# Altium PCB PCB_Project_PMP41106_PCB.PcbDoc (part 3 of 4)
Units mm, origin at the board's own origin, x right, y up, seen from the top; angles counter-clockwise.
Board outline 190 x 100 mm, 2 copper layers (Top Layer, Bottom Layer), stack 1.646 mm thick; 219 components, 122 nets, 541 pads, 61 vias.
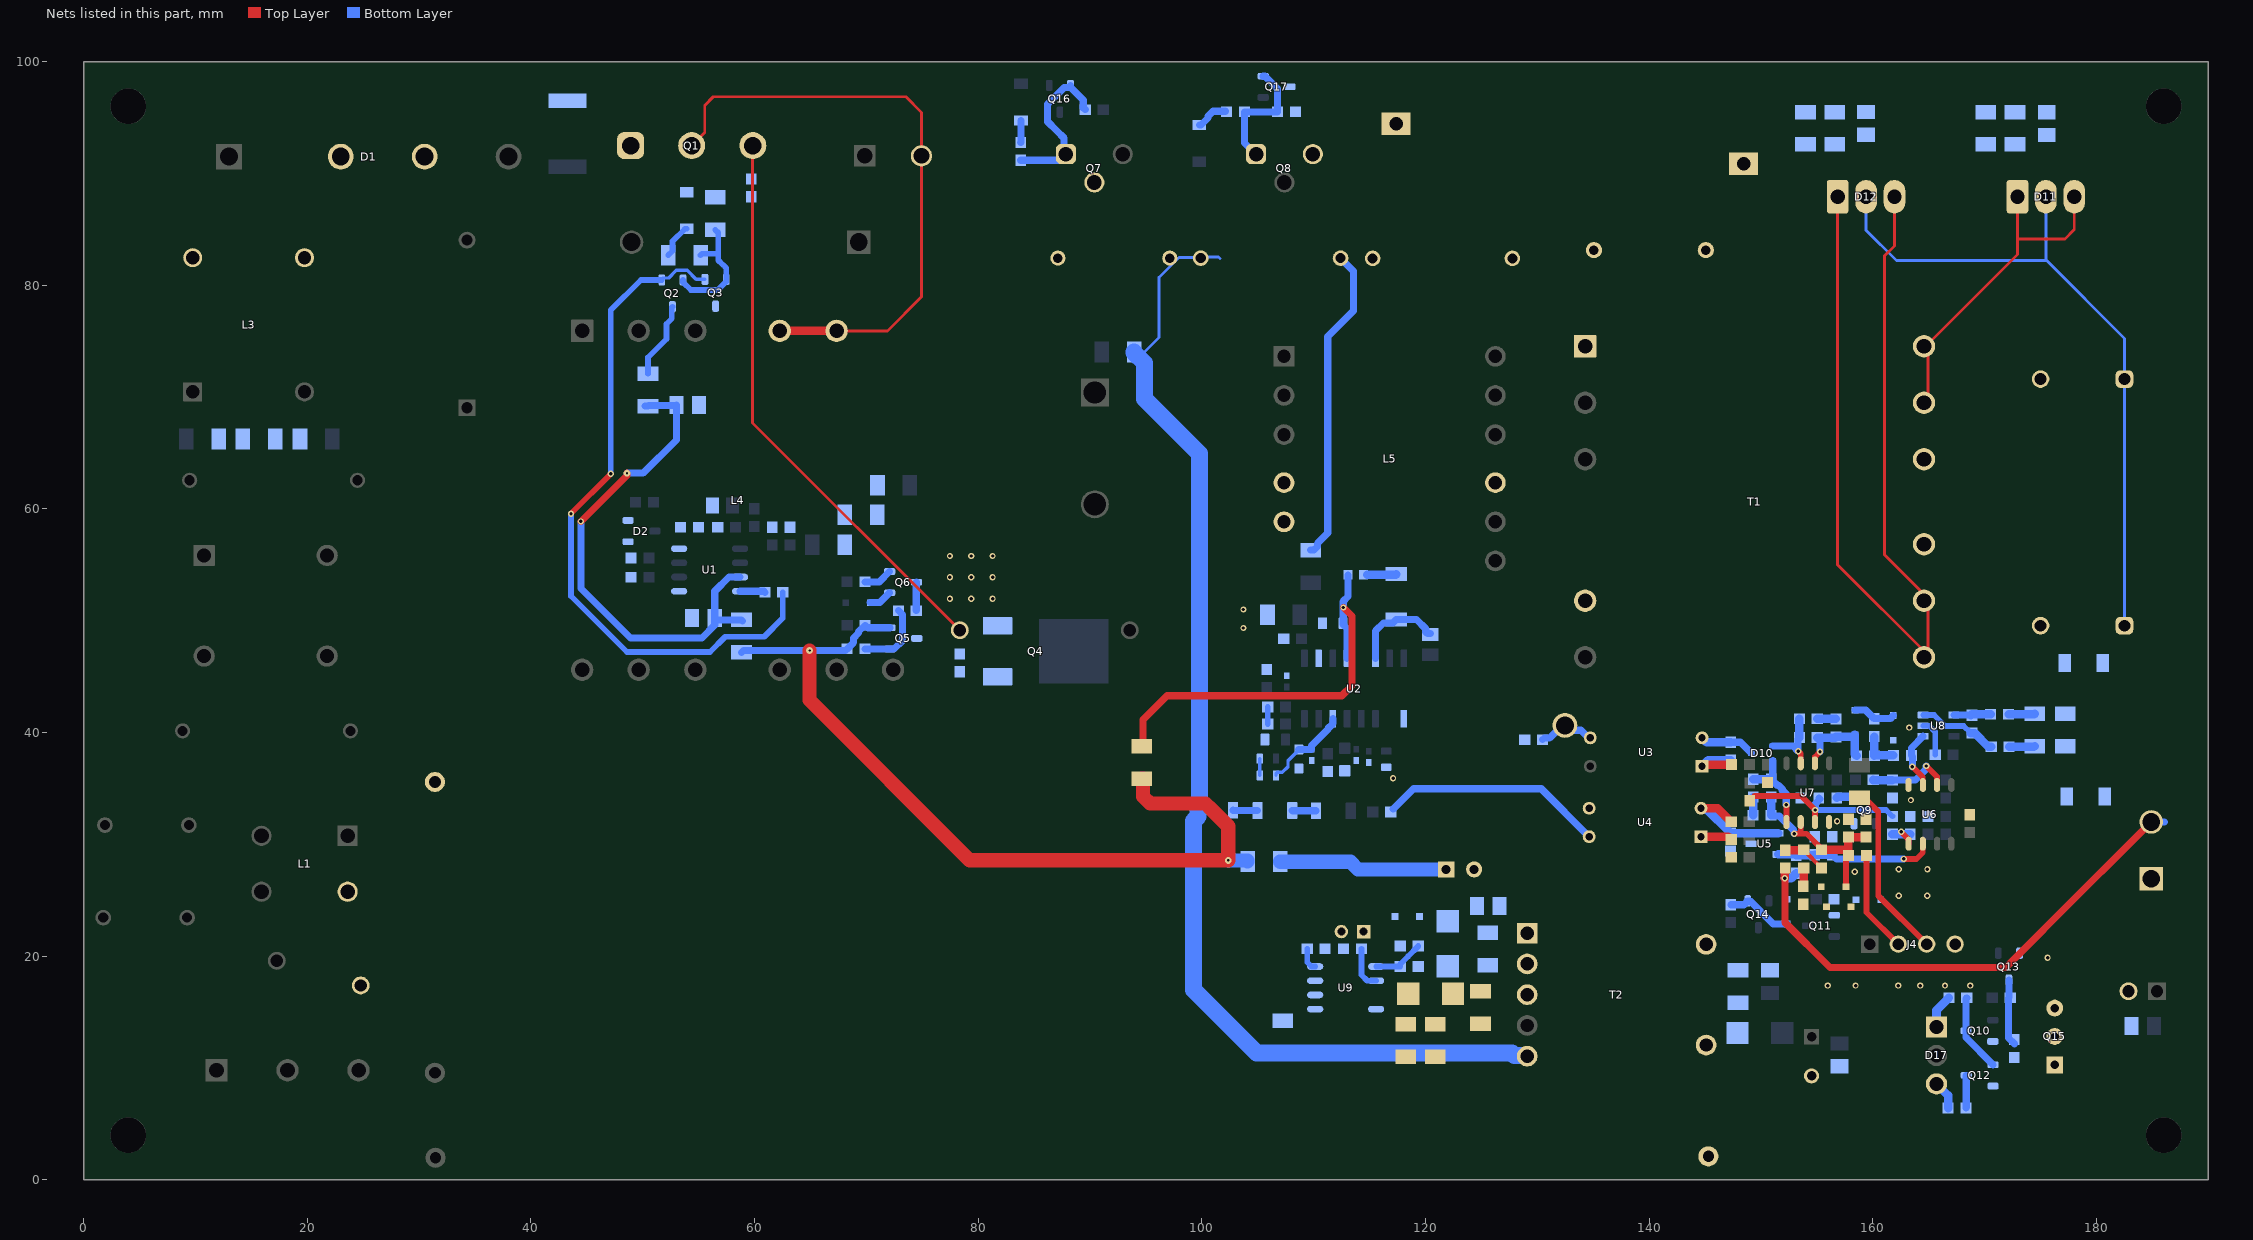
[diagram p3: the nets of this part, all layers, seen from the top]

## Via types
v1: diameter 0.559, hole 0.305, Top Layer to Bottom Layer, tented both sides, 50 vias
v2: diameter 0.61, hole 0.203, Top Layer to Bottom Layer, tented both sides, 9 vias
v3: diameter 0.559, hole 0.305, Top Layer to Bottom Layer, 2 vias

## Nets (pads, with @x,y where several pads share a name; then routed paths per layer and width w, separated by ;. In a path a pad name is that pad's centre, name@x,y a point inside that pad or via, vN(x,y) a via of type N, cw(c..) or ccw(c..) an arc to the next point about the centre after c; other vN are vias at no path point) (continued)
NetC17_2: C17.2 R27.1 R28.1 U2.12 | length 37.4
  Top Layer w0.635: R28.1@94.615,38.788 94.742,38.915 94.742,41.148 96.884,43.29 112.505,43.29 113.411,44.196 113.411,50.419 v3(112.649,51.181)
  Top Layer w1.27: R28.1@94.488,38.803 94.503,38.788 R28.1@94.615,38.788
  Bottom Layer w0.635: C17.2@112.634,49.659 112.979,49.314 U2.12@112.979,46.636 ; C17.2@112.634,49.784 112.634,51.736 113.067,52.168 R27.1@113.067,54.102
NetC18_2: C18.2 D9.1 U2.14 | length 8.4
  Bottom Layer w0.635: U2.14@115.519,46.636 115.519,49.098 116.225,49.804 117.071,49.804 D9.1@117.373,50.106 119.185,50.106 120.014,49.277 120.014,49.011 120.155,48.87 C18.2@120.421,48.87
NetC19_1: C19.1 R35.1 R37.2 U2.6 | length 8.1
  Bottom Layer w0.305: R35.1@106.626,36.165 106.626,36.34 106.748,36.462 107.201,36.462 107.696,36.957 107.696,37.478 108.661,38.443 R37.2@108.661,38.493
  Bottom Layer w0.635: R37.2@108.661,38.493 108.667,38.498 C19.1@109.804,38.498 109.804,38.824 111.257,40.277 111.257,40.344 111.709,40.796 U2.6@111.709,41.236
NetC22_2: C22.2 C23.1 C24.1 T1.5 | length 28.2
  Bottom Layer w0.635: C24.1@109.728,56.314 110.003,56.314 110.335,56.647 110.335,56.921 111.252,57.838 111.252,75.422 113.538,77.708 113.538,81.282 C22.2@112.447,82.372
NetC27_1: C27.1 R42.1 U4.2 U5.1 | length 11
  Top Layer w0.762: U4.2@144.624,33.23 146.114,33.23 R42.1@147.333,32.011
  Bottom Layer w0.762: U4.2@144.624,33.23 145.047,33.23 C27.1@147.269,31.007 147.272,31.005 U5.1@151.517,31.005
NetC29_1: C29.1 R43.1 R44.2 U5.2 U6.6 | length 14.2
  Top Layer w0.508: v1(162.763,28.702) 163.881,28.702 164.465,29.286 U6.6@164.465,30.065
  Bottom Layer w0.635: C29.1@156.362,29.077 156.737,28.702 v1(162.763,28.702)
  Bottom Layer w0.762: U5.2@151.517,29.105 153.058,29.105 R43.1@153.137,29.026 154.737,29.026 R44.2@154.788,29.077 C29.1@156.362,29.077
NetC31_1: C31.1 C34.2 D10.2 U7.1 | length 7.8
  Top Layer w0.508: v1(152.248,33.535) 152.248,33.382 152.273,33.357 U7.1@152.273,32.002
  Bottom Layer w0.635: D10.2@151.039,37.507 151.039,35.894 150.939,35.795 151.484,35.251 151.591,35.251 151.894,34.948 151.894,34.841 152.248,34.487 v1(152.248,33.535)
  Bottom Layer w0.762: C31.1@149.301,35.833 C34.2@150.901,35.833 C34.2@150.939,35.795
NetC31_2: C31.2 R53.2 | length 1.6
  Bottom Layer w0.762: R53.2@149.289,32.62 149.301,32.633 C31.2@149.301,34.233
NetC32_1: C32.1 C33.2 D10.1 U7.7 | length 6.6
  Top Layer w0.508: v1(153.314,38.335) 153.543,38.107 U7.7@153.543,37.252
  Bottom Layer w0.635: D10.1@151.039,38.807 152.842,38.807 v1(153.314,38.335) 153.314,39.44 C33.2@153.429,39.554
  Bottom Layer w0.762: C33.2@153.429,39.554 C32.1@153.429,41.231
NetC32_2: C32.2 R54.1 | length 1.7
  Bottom Layer w0.762: C32.2@155.029,41.231 155.042,41.218 R54.1@156.693,41.218
NetC33_1: C33.1 D13.1 R54.2 R60.1 U7.6 | length 8
  Top Layer w0.508: U7.6@154.813,37.252 154.813,37.827 v1(155.27,38.284)
  Bottom Layer w0.635: C33.1@155.029,39.554 155.27,39.313 v1(155.27,38.284)
  Bottom Layer w0.762: C33.1@155.029,39.554 156.629,39.554 R54.2@156.693,39.618 158.212,39.618 D13.1@158.394,39.801 158.394,38.069 R60.1@158.534,37.929
NetC37_2: C37.2 R48.2 R49.2
NetC38_2: C38.2 R50.2 R51.2
NetC40_1: C40.1 R60.2 R61.2 | length 3.4
  Bottom Layer w0.762: C40.1@160.122,39.643 160.134,39.631 R60.2@160.134,37.929 160.16,37.954 R61.2@161.836,37.954
NetC40_2: C40.2 D13.2 D15.1 | length 3.9
  Bottom Layer w0.635: D13.2@158.394,42.001 159.364,42.001 C40.2@160.122,41.243 161.549,41.243 D15.1@161.823,41.518
NetC42_1: C42.1 R87.1 | length 1.8
  Top Layer w0.762: C42.1@153.721,26.251 C42.1@153.81,26.34 ; C42.1@153.772,26.251 153.81,26.289 C42.1@153.81,26.34 ; R87.1@153.81,27.921 R87.1@153.81,27.889 C42.1@153.81,26.34
NetC42_2: C42.2 D14.1 D16.2
NetC45_1: C45.1 R67.1 U8.4 | length 3.3
  Bottom Layer w0.635: U8.4@167.237,41.571 168.735,41.571 C45.1@168.758,41.548
  Bottom Layer w0.762: C45.1@168.758,41.548 168.847,41.637 R67.1@170.523,41.637
NetC45_2: C45.2 R70.1 U8.3 | length 7.3
  Bottom Layer w0.508: U8.3@164.487,41.571 165.471,41.571 166.448,40.594 168.112,40.594 C45.2@168.758,39.948
  Bottom Layer w0.762: C45.2@168.758,39.948 169.1,39.948 170.332,38.716 R70.1@170.574,38.716
NetC46_2: C46.2 J2.1 R68.2 R69.2 R70.2 | length 2.3
  Bottom Layer w0.762: R70.2@172.174,38.716 174.399,38.716 R68.2@174.473,38.79
NetC48_1: C48.1 C50.1 D19.1 U9.6 | length 3.9
  Bottom Layer w0.508: C50.1@114.262,20.682 114.262,18.333 114.783,17.812 U9.6@115.577,17.812
NetC49_1: C49.1 C51.2 D19.2 D20.1 R74.2 | length 15.1
  Bottom Layer w1.27: R74.2@106.987,28.473 106.987,28.463 107.002,28.448 113.284,28.448 113.963,27.769 C49.1@121.838,27.769
NetC51_1: C51.1 R75.1
NetC52_2: C52.2 D21.1 R76.1
NetC53_2: C53.2 R81.2
NetC56_2: C56.2 J3.2 Q15.3
NetD1_2: D1.2 L3.4
NetD1_3: D1.3 L3.3
NetD4_1: D4.1 R12.2 | length 3.1
  Bottom Layer w0.508: R12.2@52.271,82.677 52.667,83.073 52.667,83.936 53.772,85.04 D4.1@53.924,85.04
NetD4_2: D4.2 Q1.1 R8.2 R9.2
NetD5_2: D5.2 L4.4 L4.5 Q1.2 | length 54.8
  Top Layer w0.254: Q1.2@54.356,92.488 55.539,93.671 55.539,96.081 56.308,96.85 73.533,96.85 74.93,95.453 74.93,91.421 74.93,78.969 71.88,75.918 L4.5@67.332,75.918
  Top Layer w0.762: L4.4@62.252,75.918 L4.5@67.332,75.918
NetD6_2: D6.2 Q6.1 | length 2.1
  Bottom Layer w0.635: D6.2@70.34,51.619 71.2,51.619 Q6.1@72.079,52.498
NetD7_1: D7.1 R29.1 | length 2
  Bottom Layer w0.635: R29.1@83.795,92.773 83.807,92.786 83.807,94.717 D7.1@83.82,94.73
NetD8_1: D8.1 R30.1 | length 2.9
  Bottom Layer w0.635: D8.1@99.771,94.322 99.924,94.322 100.555,94.953 100.555,95.106 101.004,95.555 R30.1@102.095,95.555
NetD9_2: D9.2 R27.2 | length 2.6
  Bottom Layer w0.762: R27.2@114.783,54.102 117.329,54.102 D9.2@117.373,54.146
NetD10_3: D10.3 R41.2 U3.2 | length 5
  Bottom Layer w0.635: R41.2@147.295,39.135 148.161,39.135 D10.3@149.139,38.157
  Bottom Layer w0.762: U3.2@144.725,39.529 145.119,39.135 R41.2@147.295,39.135
NetD11_1: D11.1 D11.3 R48.1 R49.1 T1.11 T1.12 | length 29.8
  Top Layer w0.254: T1.11@164.922,69.665 164.922,74.745 172.923,82.746 172.923,84.131 ; D11.1@172.923,87.865 172.923,84.131 ; D11.3@178.003,87.865 178.003,84.97 177.165,84.131 172.923,84.131
NetD12_1: D12.1 D12.3 R50.1 R51.1 T1.7 T1.8 | length 87.3
  Top Layer w0.254: D12.1@156.845,87.916 156.845,55.012 164.922,46.935 164.922,52.015 161.036,55.901 161.036,82.633 161.925,83.522 D12.3@161.925,87.916
NetD17_1: D17.1 R71.2 | length 3.1
  Bottom Layer w0.762: D17.1@165.684,13.665 165.684,15.176 R71.2@166.789,16.281
NetD17_3: D17.3 R72.2 | length 2.6
  Bottom Layer w0.762: D17.3@165.684,8.585 166.713,7.556 R72.2@166.713,6.426
NetD18_1: D18.1 Q11.1 R73.2
NetD20_2: D20.2 R75.2 R79.2 T2.2
NetD21_2: D21.2 R77.2
NetD22_2: D22.2 R81.1 T2.7
NetD23_1: D23.1 Q14.1 R82.2 | length 6.1
  Bottom Layer w0.635: R82.2@147.295,24.606 148.459,24.606 Q14.1@148.808,24.956 149.016,24.956 151.087,22.884 D23.1@152.349,22.884
NetF1_1: F1.1 L1.2 RV1.1 | length 0
  Top Layer w0.254: RV1.1@24.781,17.391 RV1.1@24.79,17.4
NetI_OPTO_1: I_OPTO.1 R38.2 U3.3 | length 5.1
  Bottom Layer w0.635: R38.2@130.467,39.37 130.624,39.528 131.095,39.528 132.08,40.513 132.588,40.513 132.889,40.212 133.903,40.212 134.586,39.529 U3.3@134.725,39.529
NetJ4_2: J4.2 R86.1 | length 9.1
  Top Layer w0.508: R86.1@159.423,29.007 159.423,23.925 J4.2@162.266,21.082
NetJ4_3: J4.3 R85.2 | length 15.8
  Top Layer w0.508: R85.2@158.801,34.174 159.222,34.174 160.477,32.918 160.477,25.411 J4.3@164.806,21.082
NetL5_9: L5.9 T1.1
NetQ2_1: Q2.1 Q3.1 R11.2 | length 61.8
  Top Layer w0.508: v1(43.586,59.57) 43.586,59.579 47.142,63.135 v1(47.142,63.144)
  Bottom Layer w0.305: Q2.1@51.704,80.473 51.704,80.497 51.852,80.645 52.324,80.645 53.005,81.326 53.962,81.326 54.764,80.524 Q3.1@55.565,80.524
  Bottom Layer w0.508: v1(43.586,59.57) 43.586,52.204 48.59,47.2 56.007,47.2 57.379,48.571 60.858,48.571 62.522,50.235 R11.2@62.522,52.534 ; v1(47.142,63.144) 47.142,77.775 49.841,80.473 Q2.1@51.704,80.473
NetQ2_2: Q2.2 Q3.2 R9.1 R12.1 | length 11.3
  Bottom Layer w0.508: Q2.2@53.604,80.473 53.604,80.273 54.307,79.57 56.711,79.57 57.465,80.324 Q3.2@57.465,80.524 57.465,81.544 57.167,81.841 57.142,81.841 56.746,82.237 56.746,82.804 ; R12.1@55.171,82.677 55.298,82.804 56.746,82.804 ; R9.1@56.49,84.949 56.746,84.692 56.746,82.804
NetQ2_3: Q2.3 R13.2 | length 6.9
  Bottom Layer w0.508: R13.2@50.47,72.087 50.47,73.546 52.121,75.197 52.121,76.538 52.608,77.025 52.608,78.027 Q2.3@52.654,78.073
NetQ4_1: Q4.1 Q5.3 R20.2
NetQ5_1: Q5.1 R21.1 R22.2 | length 6.5
  Bottom Layer w0.635: R21.1@69.863,47.479 72.094,47.479 Q5.1@72.104,47.469 72.481,47.469 73.228,48.216 73.228,50.54 R22.2@72.86,50.908
NetQ6_3: Q6.3 R22.1 | length 2.5
  Bottom Layer w0.635: R22.1@74.46,50.908 74.46,53.429 Q6.3@74.479,53.448
NetQ7_1: Q7.1 Q16.2 R29.2 R33.2 | length 14.9
  Bottom Layer w0.635: R29.2@83.795,91.173 87.26,91.173 87.812,91.726 87.884,91.726 87.684,91.926 87.684,93.139 86.995,93.828 86.208,94.615 86.208,96.206 87.692,97.69 88.232,97.69 Q16.2@88.25,97.707 ; Q16.2@88.25,97.872 Q16.2@88.25,97.707 ; R33.2@89.573,95.707 89.548,95.707 89.391,95.865 89.391,96.566 Q16.2@88.25,97.707
NetQ8_1: Q8.1 Q17.2 R30.2 R34.2 | length 10.9
  Bottom Layer w0.635: Q8.1@104.724,91.726 104.724,91.798 103.797,92.725 R30.2@103.797,95.504 R34.2@106.769,95.504 106.769,97.565 105.645,98.689 Q17.2@105.48,98.689
NetQ9_3: Q9.3 R55.1 | length 2.5
  Bottom Layer w0.762: R55.1@156.769,34.157 156.864,34.252 Q9.3@159.258,34.252
NetQ10_3: Q10.3 Q12.1 R71.1 | length 7
  Bottom Layer w0.635: R71.1@168.389,16.281 168.32,16.212 Q10.3@168.32,13.335 168.32,12.723 Q12.1@170.745,10.297
NetQ12_3: Q12.3 R72.1 | length 2.9
  Bottom Layer w0.635: R72.1@168.313,6.426 168.345,6.458 Q12.3@168.345,9.347
NetQ13_3: Q13.3 Q15.2 R83.1 R84.2 | length 5.9
  Bottom Layer w0.635: Q13.3@172.161,17.875 172.161,16.32 172.123,16.281 172.123,12.7 R84.2@172.644,12.179
NetR1_1: R1.1 R2.2
NetR2_1: R2.1 R3.2
NetR6_2: R6.2 U1.4
NetR11_1: R11.1 U1.8 | length 2.3
  Bottom Layer w0.635: U1.8@58.707,52.635 60.82,52.635 R11.1@60.922,52.534
NetR14_1: R14.1 R15.2
NetR15_1: R15.1 R16.2
NetR23_1: R23.1 R24.2 | length 1.5
  Bottom Layer w0.508: R23.1@105.88,40.767 R24.2@105.88,42.291
NetR32_1: R32.1 R35.2 | length 1.5
  Bottom Layer w0.305: R35.2@105.176,36.165 R32.1@105.176,37.663
NetR36_1: R36.1 U4.4 | length 20
  Bottom Layer w0.635: R36.1@117.108,33.161 118.923,34.976 130.338,34.976 U4.4@134.624,30.69
NetR39_1: R39.1 U4.1 | length 2.8
  Top Layer w0.762: U4.1@144.624,30.69 147.079,30.69 R39.1@147.333,30.436
NetR40_1: R40.1 R41.1 U3.1 | length 5.5
  Top Layer w0.762: U3.1@144.725,36.989 144.878,37.141 R40.1@147.358,37.141
  Bottom Layer w0.762: U3.1@144.725,36.989 145.272,37.535 R41.1@147.295,37.535
NetR45_1: R45.1 R46.2 U6.5 | length 2.9
  Top Layer w0.508: v1(162.535,31.122) 163.195,30.461 U6.5@163.195,30.065
  Bottom Layer w0.762: R45.1@161.747,30.906 R46.2@163.347,30.906
NetR58_1: R58.1 R59.2 U6.2 | length 7.5
  Top Layer w0.508: v1(164.77,37.014) 165.735,36.049 U6.2@165.735,35.315
  Bottom Layer w0.635: R59.2@161.747,35.757 163.792,35.757 164.77,36.735 v1(164.77,37.014)
  Bottom Layer w0.762: R58.1@160.033,35.77 160.045,35.757 R59.2@161.747,35.757
NetR61_1: R61.1 U6.3 U8.1 | length 5.2
  Top Layer w0.508: v1(163.525,36.938) 164.465,35.998 U6.3@164.465,35.315
  Bottom Layer w0.635: v1(163.525,36.938) 163.525,37.865 R61.1@163.436,37.954 163.436,38.62 U8.1@164.487,39.671
NetR63_1: R63.1 R64.2 R87.2 | length 3.9
  Top Layer w0.381: R64.2@153.81,29.521 153.81,29.489 R87.2@155.41,27.889
  Top Layer w0.762: R63.1@152.171,29.483 153.772,29.483 R64.2@153.81,29.521
NetR77_1: R77.1 T2.3 U9.8
NetR78_2: R78.2 U9.4 | length 2.1
  Bottom Layer w0.508: R78.2@109.411,20.657 109.411,19.476 109.804,19.082 U9.4@110.127,19.082
NetR88_1: R88.1 R89.2 | length 2.2
  Bottom Layer w0.635: R88.1@102.769,33.052 102.782,33.039 104.965,33.039 R89.2@104.978,33.027
NetR89_1: R89.1 R90.2 | length 2.1
  Bottom Layer w0.635: R89.1@108.078,33.027 108.09,33.014 110.197,33.014 R90.2@110.21,33.001
PGND: C3.2 C4.2 C6.2 C7.2 C8.2 C9.2 C10.2 C12.2 C13.2 C14.2 C15.1 C16.2 C17.1 C19.2 C20.2 C21.2 C23.2 C28.2 C30.2 C48.2 C49.2 C50.2 C58.2 D2.1 D2.2 H1.1 L5.4 L5.5 Q1.3 Q3.3 Q4.3 Q6.2 Q8.3 Q17.3 R6.1 R7.2 R8.1 R17.1 R20.1 R25.1 R26.1 R31.1 R34.1 R37.1 R38.1 R78.1 R80.1 R91.1 RF1.2 T2.1 U1.1 U2.1 U2.10 U4.3 U9.1 U9.2 U9.3 | length 53.6
  Top Layer w0.254: Q1.3@59.817,92.488 59.817,67.692 RF1.2@78.354,49.156
  Bottom Layer w0.635: C12.2@69.863,53.474 71.154,53.474 Q6.2@72.079,54.398
  other v1: 117.094,35.922 103.708,49.352 103.708,51.003 77.47,51.975 79.375,51.975 81.28,51.975 77.47,53.88 79.375,53.88 81.28,53.88 77.47,55.785 79.375,55.785 81.28,55.785
SGND: C27.2 C29.2 C30.1 C35.2 C36.1 C39.2 C41.2 C43.2 C44.2 C47.2 C54.2 C55.2 C57.2 D14.2 D15.2 D18.2 D23.2 H2.1 J4.4 pad.1@145.288,2.108 Q9.2 Q10.2 Q12.2 Q13.2 Q15.1 R44.1 R46.1 R52.1 R59.1 R62.1 R65.1 R67.2 R68.1 R69.1 R84.1 T1.9 T1.10 T2.6 U5.3 U6.4 U7.4 U8.2 | length 5.8
  Bottom Layer w0.508: U8.2@164.487,40.621 165.024,40.621 165.57,40.075 C47.2@165.57,38.005
  Bottom Layer w0.762: R67.2@172.123,41.637 174.42,41.637 R68.1@174.473,41.69
  other v1: 155.956,17.374 158.445,17.374 162.255,17.374 164.236,17.374 166.446,17.374 168.707,17.374 175.616,19.863 162.306,25.4 164.846,25.4 158.369,27.559 162.306,27.788 164.871,27.788 156.794,32.061 163.398,33.96 163.246,40.443
VBIAS: C34.1 D16.1 R53.1 R62.2 R64.1 R65.2 R86.2 U7.2 | length 16.8
  Top Layer w0.508: v1(152.959,30.963) 153.543,30.963 ; U7.2@153.543,32.002 153.543,30.963 ; R64.1@155.41,29.521 155.41,29.61 154.058,30.963 153.543,30.963 ; D16.1@157.589,26.213 157.589,28.773 R86.2@157.823,29.007
  Top Layer w0.762: R64.1@155.41,29.521 157.727,29.521 157.81,29.439 R65.2@157.81,30.652 R62.2@159.385,30.652
  Bottom Layer w0.635: R53.1@150.889,32.62 150.962,32.547 151.628,32.547 152.959,31.217 v1(152.959,30.963)
  Bottom Layer w0.762: R53.1@150.889,32.62 150.901,32.633 C34.1@150.901,34.233
VBUS: C14.1 C22.1 C52.1 C58.1 Q7.2 R18.2 R76.2 R88.2 T2.5 | length 105.7
  Bottom Layer w0.254: R18.2@94.516,73.667 96.164,75.315 96.164,80.706 97.504,82.045 97.939,82.48 C22.1@99.947,82.48 ; C22.1@99.895,82.531 101.475,82.531 101.602,82.404
  Bottom Layer w1.524: R18.2@93.931,74.022 93.931,73.971 94.869,73.034 94.869,69.85 99.769,64.95 R88.2@99.769,33.052 ; R88.2@99.669,33.052 99.669,32.517 99.263,32.112 99.263,16.993 104.904,11.352 C58.1@107.239,11.352 ; C58.1@107.402,11.352 127.72,11.352 127.964,11.108 129.037,11.108 T2.5@129.084,11.061
VCC: Q5.2 R4.1 R19.2 R21.2 R28.2 R74.1 | length 77.8
  Top Layer w1.27: v2(64.922,47.346) 64.922,42.901 79.248,28.575 v2(102.362,28.575) 102.362,31.623 100.837,33.148 100.33,33.655 95.377,33.655 94.742,34.29 94.742,35.873 94.727,35.888 R28.2@94.615,35.888
  Bottom Layer w0.635: R4.1@58.826,47.172 59,47.346 v2(64.922,47.346) 68.129,47.346 R21.2@68.263,47.479 68.288,47.479 68.845,48.037 68.845,48.438 69.306,48.898 69.306,49.03 69.863,49.587 R19.2@69.888,49.587 69.913,49.587 70.131,49.369 Q5.2@72.104,49.369
  Bottom Layer w1.27: v2(102.362,28.575) 104.072,28.55 104.087,28.535 R74.1@104.087,28.473
VCC_PFC: C3.1 C10.1 R4.2 R13.1 U1.7 | length 46.3
  Top Layer w0.635: v1(44.475,58.884) 48.59,62.999 v2(48.59,63.195)
  Bottom Layer w0.635: v1(44.475,58.884) 44.475,52.889 48.895,48.47 55.296,48.47 56.439,49.613 C3.1@56.439,50.248 ; v2(48.59,63.195) 50.038,63.195 53.01,66.167 C10.1@53.01,69.291 52.958,69.239 50.522,69.239 R13.1@50.47,69.187 R13.1@50.195,69.187 ; U1.7@58.707,53.905 57.709,53.905 56.439,52.635 C3.1@56.439,50.248 ; R4.2@58.93,49.968 R4.2@58.826,50.072 56.614,50.072 C3.1@56.439,50.248
VOUT: C37.1 C38.1 C39.1 C41.1 C44.1 C46.1 D11.2 D12.2 J2.2 R43.2 R63.2 | length 108.5
  Top Layer w0.635: v1(152.121,26.981) 152.121,23.038 156.159,18.999 171.875,18.999 174.76,21.884 175.887,23.011 J2.2@184.887,32.011
  Top Layer w0.762: v1(152.121,26.981) 152.121,27.832 R63.2@152.171,27.883
  Bottom Layer w0.254: D12.2@159.385,87.916 159.385,84.919 162.103,82.201 175.539,82.201 ; D11.2@175.463,87.865 175.463,82.277 175.539,82.201 ; C39.1@182.49,49.562 C41.1@182.49,71.609 182.49,75.251 175.539,82.201
  Bottom Layer w0.635: J2.2@184.887,32.011 186.048,32.011
  Bottom Layer w0.762: v1(152.121,26.981) 152.692,26.981 R43.2@153.137,27.426
VREF: R45.2 R56.2 R57.2 U7.3 | length 16.1
  Top Layer w0.508: R56.2@148.996,33.903 149.415,34.322 153.594,34.322 v1(154.838,33.077) 154.813,33.052 U7.3@154.813,32.002
  Bottom Layer w0.508: v1(154.838,33.077) 161.176,33.077 R45.2@161.747,32.506
  Bottom Layer w0.635: v1(154.838,33.077) 154.838,33.624 155.27,34.055 R57.2@155.169,34.157
VS: R79.1 R80.2 U9.5 | length 4.7
  Bottom Layer w0.508: U9.5@115.577,19.082 R79.1@117.742,19.082 117.742,19.311 118.413,19.982 118.43,19.982 119.342,20.894 R80.2@119.342,20.911
pads on no net: L4.7 L4.8 L4.9 L4.10 L4.11 L4.12 L5.1 L5.2 L5.7 L5.8 L5.10 L5.11 L5.12 T1.2 T1.3 T1.6 T2.4
copper on no net:
  other v1: 147.269,27.711 150.216,29.598

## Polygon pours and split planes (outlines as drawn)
VBUS on Top Layer "Top Layer-No Net 18" (solid, pour order 154): 117.246,11.97 129.667,11.97 129.997,11.64 129.997,10.624 129.667,10.294 117.272,10.294 117.094,10.471 117.094,11.818
PGND on Top Layer "Top Layer-No Net 19" (solid, pour order 156): 96.799,35.795 100.889,39.885 107.975,39.885 109.15,38.71 113.621,38.71 114.605,37.726 114.605,33.966 115.011,33.56 116.129,33.56 116.611,34.043 116.611,36.837 117.17,37.395 118.745,37.395 120.04,36.1 126.873,36.1 130.251,32.722 130.251,21.851 130.251,21.343 129.667,20.758 127.102,20.758 125.578,19.234 115.519,19.234 114.122,17.837 114.122,15.069 112.954,13.9 101.321,13.9 96.799,18.422
NetL5_9 on Top Layer "TOP_LAYER_NETL5_9_P216" (solid, pour order 216): 125.07,60.985 125.07,63.348 125.908,64.186 127.305,64.186 128.092,64.973 128.092,75.26 130.302,77.47 136.601,77.47 138.76,75.311 138.76,73.533 137.541,72.314 132.893,72.314 131.216,70.637 131.216,63.449 128.803,61.036
HS on Top Layer "Top Layer-No Net 12" (solid, pour order 112): 106.756,90.195 107.848,90.195 108.28,89.764 108.28,65.862 107.569,65.151 104.267,65.151 101.727,67.691 101.727,83.439 99.739,85.427 97.936,85.427 92.024,91.338 92.024,92.513 92.856,93.345 94.698,93.345 98.559,89.484 106.045,89.484
"L Wire" on Top Layer "Top Layer-No Net" (solid, remove dead copper, pour order 196): 23.33,10.541 25.006,12.217 31.839,12.217 32.779,11.278 32.779,8.788 32.144,8.153 23.685,8.153 23.33,8.509
"L Wire" on Top Layer "Top Layer-No Net" (solid, remove dead copper, pour order 2): 23.33,10.541 25.006,12.217 31.839,12.217 32.779,11.278 32.779,8.788 32.144,8.153 23.685,8.153 23.33,8.509
NetC5_1 on Top Layer "Top Layer-No Net 9" (solid, pour order 70): 10.719,94.742 15.164,99.187 43.466,99.187 45.06,97.593 45.06,89.338 48.463,85.935 49.86,85.935 56.032,79.763 56.032,75.006 54.159,73.133 42.113,73.133 36.805,67.825 33.274,67.825 32.334,68.764 32.334,72.574 39.395,79.636 41.834,82.074 41.834,86.29 41.834,86.824 41.834,94.317 40.919,95.231 19.158,95.231 13.624,89.697 11.655,89.697 10.719,90.634
NetD5_2 on Top Layer "Top Layer-No Net 11" (solid, remove dead copper, pour order 80): 52.73,97.111 54.857,99.238 74.86,99.238 78.461,95.638 78.461,77.045 74.981,73.565 62.579,73.565 61.011,75.133 61.011,77.775 62.541,79.305 71.323,79.305 72.949,80.931 72.949,93.326 71.247,95.028 57.226,95.028 56.261,94.063 56.261,91.243 55.397,90.38 53.619,90.38 52.73,91.269
SGND on Top Layer "Top Layer-No Net 21" (solid, remove dead copper, pour order 212): 176.704,75.142 172.462,75.142 169.897,72.577 169.897,68.589 168.068,66.76 162.835,66.76 161.921,65.846 161.921,56.727 164.41,54.238 167.128,54.238 168.296,53.07 168.296,45.374 166.366,43.443 147.545,43.443 144.395,40.294 144.42,40.268 144.42,12.963 144.065,12.608 144.065,1.755 145.055,0.765 180.329,0.765 189.556,9.991 189.556,20.99 186.889,23.657 182.495,23.657 178.863,27.289 178.863,72.983
NetD1_2 on Top Layer "Bottom Layer-No Net 13" (solid, pour order 206): 10.522,87.154 14.605,87.154 17.78,90.329 20.161,92.71 24.054,92.71 25.07,91.694 25.07,90.075 22.149,87.154 19.075,87.154 11.303,79.382 9.068,79.382 9.042,79.356 8.204,79.356 6.883,80.677 6.883,83.515
NetD1_3 on Top Layer "Bottom Layer-No Net 12" (solid, remove dead copper, pour order 198): 23.368,84.512 28.219,89.364 28.219,91.669 29.261,92.71 32.436,92.71 33.452,91.694 33.452,87.84 24.994,79.382 19.406,79.382 18.491,80.296 18.491,81.16 18.491,82.785 20.218,84.512
VOUT on Top Layer "Top Layer-No Net 20" (solid, remove dead copper, pour order 190): 181.407,76.562 186.512,76.562 188.392,74.683 188.392,31.477 187.223,30.309 183.236,30.309 179.756,33.789 179.756,74.911
PGND on Top Layer "Top Layer-No Net 14" (solid, pour order 132): 59.436,93.91 58.903,93.91 58.115,93.123 58.115,89.669 56.439,87.992 53.746,87.992 52.73,86.976 52.73,72.27 49.276,68.815 43.434,68.815 37.922,63.303 37.922,40.57 42.647,35.846 77.394,35.846 85.903,44.355 85.903,70.593 89.256,73.946 89.256,74.048 84.125,79.178 76.302,71.355 65.557,71.355 63.017,73.895 63.043,73.921 63.043,93.148 62.281,93.91
PGND on Top Layer "Top Layer-No Net 13" (solid, remove dead copper, pour order 118): 108.839,91.059 108.839,86.494 110.617,84.716 115.113,84.716 116.408,83.42 116.408,81.16 115.291,80.042 111.609,80.042 110.261,78.695 110.261,73.667 108.534,71.939 104.165,71.939 101.879,74.225 101.879,78.975 100.813,80.042 96.672,80.042 95.174,81.541 95.174,82.531 92.354,85.351 85.903,85.351 82.144,81.591 82.144,77.114 85.312,73.946 92.608,73.946 94.005,72.549 94.005,70.39 94.005,54.312 99.644,48.673 113.284,48.673 113.894,49.283 113.894,49.918 119.812,49.918 120.574,49.918 124.333,49.918 125.044,50.629 125.044,76.613 128.473,80.042 134.798,80.042 135.763,81.007 135.763,84.309 134.595,85.478 129.489,85.478 119.253,95.714 112.065,95.714 109.271,92.92 108.839,92.488
NetC5_2 on Top Layer "Top Layer-No Net 10" (solid, pour order 72): 37.135,93.58 36.322,92.767 36.322,87.154 33.477,84.309 33.477,83.065 34.315,82.226 36.906,82.226 39.624,84.944 39.624,93.123 39.167,93.58
NetD12_1 on Top Layer "Top Layer-No Net 8" (solid, pour order 68): 155.27,89.542 157.582,89.542 157.886,89.237 157.886,86.392 158.521,85.757 160.249,85.757 160.884,86.392 160.884,89.237 161.188,89.542 162.687,89.542 163.551,88.678 163.551,80.017 161.163,77.629 161.163,55.988 163.728,53.423 165.913,53.423 167.462,51.873 167.462,46.463 165.887,44.888 161.468,44.888 154.178,52.178 154.178,88.449
NetD11_1 on Top Layer "Top Layer-No Net 7" (solid, remove dead copper, pour order 36): 163.043,76.562 171.018,84.538 171.018,88.653 171.882,89.516 173.634,89.516 173.965,89.186 173.965,86.062 174.32,85.706 176.606,85.706 176.962,86.062 176.962,89.186 177.292,89.516 178.664,89.516 179.527,88.653 179.527,83.75 168.91,73.133 168.91,69.044 167.462,67.596 164.719,67.596 163.043,69.272
EARTH on Top Layer "Bottom Layer-No Net 4" (solid, pour order 34): 0.559,33.789 2.946,33.789 3.378,33.357 3.378,16.51 8.426,11.462 12.338,11.462 12.954,10.846 12.954,5.791 15.494,3.251 32.207,3.251 32.944,2.515 32.944,0.94 32.41,0.406 11.913,0.406 9.195,3.124 9.195,5.918 6.198,8.915 2.648,8.915 0.102,11.462 0.102,33.331
NetC2_2 on Top Layer "Top Layer-No Net 6" (solid, remove dead copper, pour order 32): 18.542,71.965 22.327,71.965 25.959,68.333 25.959,60.611 24.74,59.392 24.74,53.829 23.978,53.067 20.447,53.067 19.787,53.728 19.787,64.929 17.983,66.732 17.983,71.406
NetC2_1 on Top Layer "Top Layer-No Net 5" (solid, remove dead copper, pour order 16): 11.836,71.965 12.268,71.533 12.268,64.573 13.36,63.481 13.36,53.728 12.725,53.093 8.661,53.093 8.026,53.728 8.026,60.662 7.188,61.5 7.188,71.482 7.671,71.965
NetC1_1 on Top Layer "Top Layer-No Net 4" (solid, pour order 14): 24.054,48.089 24.74,47.403 24.74,43.187 26.518,41.409 26.518,30.023 25.324,28.829 22.504,28.829 21.285,30.048 21.285,40.393 19.812,41.866 19.812,47.352 20.549,48.089
NetC1_2 on Top Layer "Top Layer-No Net 3" (solid, pour order 12): 12.7,48.089 13.31,47.479 13.31,43.212 18.44,38.081 18.44,30.074 17.196,28.829 14.522,28.829 10.998,25.305 10.998,23.095 10.185,22.282 8.382,22.282 7.595,23.07 7.595,24.873 14.072,31.35 14.072,36.1 12.294,37.878 8.407,37.878 7.264,39.021 7.264,47.479 7.874,48.089
"N Wire" on Top Layer "Top Layer-No Net 2" (solid, pour order 10): 17.094,8.153 16.383,8.865 16.383,15.374 13.691,18.066 13.691,25.432 15.132,26.873 17.348,26.873 18.39,25.832 18.39,22.841 20.371,20.86 20.371,8.865 19.66,8.153
NetF1_1 on Top Layer "Top Layer-No Net 1" (solid, remove dead copper, pour order 8): 21.806,23.686 23.203,22.288 23.203,15.761 24.041,14.922 26.353,14.922 27.14,15.71 27.14,20.993 29.502,23.355 32.855,26.708 32.855,35.852 32.106,36.601 29.82,36.601 29.02,35.801 29.02,29.064 27.115,27.159 22.822,27.159 21.806,26.143
NetR77_1 on Top Layer "Top Layer-No Net 15" (solid, pour order 134): 123.952,14.662 125.806,14.662 128.626,17.482 129.667,17.482 130.048,17.101 130.048,16.009 129.819,15.78 128.753,15.78 126.263,13.291 123.952,13.291 123.876,13.367 123.876,14.586
NetD21_2 on Top Layer "Top Layer-No Net 16" (solid, pour order 136): 121.463,17.685 125.705,17.685 125.857,17.533 125.857,16.237 125.73,16.11 123.774,16.11 123.444,15.78 123.342,15.678 121.539,15.678 121.463,15.755
NetC52_2 on Top Layer "Top Layer-No Net 17" (solid, pour order 138): 117.424,17.685 119.431,17.685 119.482,17.634 119.482,14.942 119.812,14.612 121.768,14.612 121.869,14.51 121.869,13.291 121.793,13.215 117.323,13.215 117.246,13.291 117.246,17.507
NetC42_2 on Top Layer "Top Layer-No Net 22" (solid, pour order 0): 153.314,24.054 153.187,24.181 153.187,25.146 153.289,25.248 154.508,25.248 154.661,25.4 154.661,26.949 154.788,27.076 155.931,27.076 156.058,26.949 156.058,25.019 156.312,24.765 156.312,24.181 156.185,24.054
NetC22_2 on Bottom Layer "BOTTOM_LAYER_NETC22_2_P222" (solid, remove dead copper, pour order 222): 131.376,60.775 136.271,55.88 136.398,55.88 136.398,51.181 134.747,49.53 130.937,49.53 128.549,51.918 128.549,56.918
PGND on Bottom Layer "BOTTOM_LAYER_PGND_P221" (solid, remove dead copper, pour order 221): 107.366,99.441 107.366,91.643 108.585,90.424 118.999,90.424 120.777,92.202 120.777,99.441
PGND on Bottom Layer "Bottom Layer-No Net 15" (solid, pour order 90): 42.189,99.727 60.884,99.727 63.729,96.882 63.729,88.881 58.75,88.881 58.09,89.542 58.09,94.114 56.82,95.384 41.707,95.384 40.894,96.196 40.894,98.432
PGND on Bottom Layer "Bottom Layer-No Net 33" (solid, pour order 130): 56.083,71.679 56.083,78.511 56.642,79.07 58.09,79.07 58.09,85.3 58.09,89.44 63.17,89.44 63.729,88.881 63.729,73.209 62.198,71.679
PGND on Bottom Layer "Bottom Layer-No Net 34" (solid, pour order 142): 56.388,63.71 62.814,63.71 64.313,62.211 64.313,58.503 63.627,57.817 61.062,57.817 60.833,58.046 60.833,61.246 60.376,61.703 57.074,61.703 56.82,61.449 56.82,59.366 57.302,58.884 57.302,54.667 55.601,52.966 55.601,51.569 55.296,51.264 55.296,49.689 54.839,49.232 49.682,49.232 46.203,52.712 46.203,59.239 46.609,59.646 49.378,59.646 49.657,59.366 49.657,53.27 49.987,52.94 53.924,52.94 54.432,53.448 54.432,61.754
NetD4_2 on Bottom Layer "Bottom Layer-No Net 17" (solid, remove dead copper, pour order 94): 47.904,93.91 49.936,93.91 50.343,93.504 50.343,90.075 51.569,88.849 60.052,88.849 60.63,88.272 60.63,86.798 59.969,86.138 51.562,86.138 47.498,90.202 47.498,93.504
SGND on Bottom Layer "Bottom Layer-No Net 7" (solid, pour order 56): 166.98,72.371 166.98,68.891 165.71,67.621 165.684,67.647 164.084,67.647 154.559,77.172 154.559,88.449 150.165,92.844 144.907,92.844 144.145,92.082 144.145,44.482 146.05,42.577 173.228,42.577 173.482,42.298 173.482,41.104 173.66,40.926 178.054,40.926 178.283,41.155 178.283,71.127 175.285,74.124 168.732,74.124
NetD22_2 on Bottom Layer "BOTTOM_LAYER_NETD22_2_P024" (solid, pour order 24): 148.869,12.167 148.844,12.192 148.844,16.864 148.43,17.279 146.526,17.279 146.158,17.647 146.158,21.786 145.688,22.256 145.687,22.255 144.409,22.255 144.018,21.786 144.018,21.643 144.018,15.037 146.888,12.167
NetC22_2 on Bottom Layer "BOTTOM_LAYER_NETC22_2_P220" (solid, pour order 220): 111.049,81.255 111.049,84.125 111.43,84.506 125.476,84.506 132.105,77.876 132.105,69.037 132.398,52.007 128.549,55.855 128.549,75.497 113.123,75.497 111.049,77.572
SGND on Bottom Layer "Bottom Layer-No Net 58" (solid, remove dead copper, pour order 217): 146.143,42.265 170.095,42.265 172.737,39.623 172.737,26.898 175.81,23.825 186.402,23.825 189.221,21.005 189.221,13.995 189.247,13.969 189.247,10.286 179.817,0.856 144.746,0.856 143.908,1.695 143.908,39.947
NetF1_1 on Bottom Layer "Top Layer-No Net 1" (solid, remove dead copper, pour order 202): 21.806,23.686 23.203,22.288 23.203,15.761 24.041,14.922 26.353,14.922 27.14,15.71 27.14,20.993 29.502,23.355 32.855,26.708 32.855,35.852 32.106,36.601 29.82,36.601 29.02,35.801 29.02,29.064 27.115,27.159 22.822,27.159 21.806,26.143
"N Wire" on Bottom Layer "Top Layer-No Net 2" (solid, pour order 200): 17.094,8.153 16.383,8.865 16.383,15.374 13.691,18.066 13.691,25.432 15.132,26.873 17.348,26.873 18.39,25.832 18.39,22.841 20.371,20.86 20.371,8.865 19.66,8.153
EARTH on Bottom Layer "Bottom Layer-No Net 4" (solid, pour order 194): 0.559,33.789 2.946,33.789 3.378,33.357 3.378,16.51 8.426,11.462 12.338,11.462 12.954,10.846 12.954,5.791 15.494,3.251 32.207,3.251 32.944,2.515 32.944,0.94 32.41,0.406 11.913,0.406 9.195,3.124 9.195,5.918 6.198,8.915 2.648,8.915 0.102,11.462 0.102,33.331
12VS on Bottom Layer "Bottom Layer-No Net 57" (solid, pour order 192): 146.609,23.552 149.479,23.552 150.901,22.13 153.645,22.13 155.194,20.581 155.194,14.662 152.502,17.355 152.502,19.412 151.765,20.149 146.888,20.149 145.999,21.038 145.999,22.943
12VS on Bottom Layer "Bottom Layer-No Net 51" (solid, pour order 178): 149.987,17.406 152.629,17.406 156.515,13.519 157.683,13.519 158.217,12.986 158.217,11.665 157.912,11.36 150.919,11.36 149.885,12.394 149.885,17.304
NetC53_2 on Bottom Layer "Bottom Layer-No Net 50" (solid, pour order 40): 147.015,19.565 151.511,19.565 151.74,19.336 151.74,18.041 151.613,17.914 147.041,17.914 146.888,18.066 146.888,19.438
10V_A on Bottom Layer "Bottom Layer-No Net 48" (solid, remove dead copper, pour order 38): 150.165,24.695 149.631,25.237 149.631,25.933 149.885,26.187 150.241,26.187 151.613,24.816 151.613,24.613 151.784,24.441 153.518,24.441 154.178,25.102 154.178,25.584 154.28,25.686 155.321,25.686 155.448,25.559 155.448,23.756 154.737,23.044 154.737,22.486 154.584,22.333 153.746,22.333 153.518,22.562 153.518,23.019 153.035,23.502 151.359,23.502
NetD18_1 on Bottom Layer "Bottom Layer-No Net 47" (solid, remove dead copper, pour order 28): 156.134,25.737 158.648,25.737 158.826,25.559 158.826,23.629 158.496,23.298 156.083,23.298 155.854,23.527 155.854,25.457
NetC48_1 on Bottom Layer "Bottom Layer-No Net 37" (solid, pour order 148): 113.767,22.841 114.808,23.883 117.602,23.883 117.704,23.781 117.704,23.121 117.272,22.689 116.281,22.689 115.646,22.054 115.646,20.581 115.265,20.2 113.817,20.2 113.767,20.25
PGND on Bottom Layer "Bottom Layer-No Net 36" (solid, pour order 146): 106.737,18.32 106.248,17.831 106.248,13.665 106.375,13.538 110.388,13.538 111.785,14.935 111.785,16.002 113.208,17.424 113.208,22.79 112.852,23.146 111.557,23.146 110.49,22.079 110.49,20.225 111.15,19.565 111.15,18.726 110.744,18.32
NetR77_1 on Bottom Layer "Bottom Layer-No Net 35" (solid, pour order 144): 126.39,15.78 128.067,17.456 129.667,17.456 130.023,17.101 130.023,16.009 129.769,15.755 128.727,15.755 126.822,13.85 114.859,13.85 114.452,14.256 114.452,15.475 114.757,15.78
NetQ4_1 on Bottom Layer "Bottom Layer-No Net 30" (solid, pour order 128): 74.041,48.8 75.032,48.8 75.235,48.597 75.235,46.311 75.565,45.981 83.007,45.981 83.236,45.752 83.236,44.228 83.033,44.025 74.828,44.025 73.812,45.041 73.812,48.571
NetR14_1 on Bottom Layer "Bottom Layer-No Net 29" (solid, pour order 126): 70.383,63.202 71.552,63.202 71.73,63.024 71.73,58.477 71.603,58.35 70.358,58.35 70.231,58.477 70.231,63.049
NetR15_1 on Bottom Layer "Bottom Layer-No Net 29" (solid, pour order 124): 67.462,60.56 68.631,60.56 68.809,60.382 68.809,55.836 68.682,55.709 67.437,55.709 67.31,55.836 67.31,60.408
NetC9_1 on Bottom Layer "Bottom Layer-No Net 27" (solid, remove dead copper, pour order 114): 57.887,55.506 60.122,55.506 60.833,56.217 60.833,57.131 61.062,57.36 64.033,57.36 64.491,57.817 65.888,57.817 65.989,57.715 65.989,55.353 65.481,54.845 65.456,54.871 57.887,54.871 57.734,55.023 57.734,55.353
NetC8_1 on Bottom Layer "Bottom Layer-No Net 26" (solid, pour order 110): 57.785,58.909 60.427,58.909 60.503,58.833 60.503,57.919 60.122,57.538 59.792,57.538 59.512,57.258 59.512,56.242 59.385,56.115 57.963,56.115 57.734,56.344 57.734,58.858
NetC7_1 on Bottom Layer "Bottom Layer-No Net 25" (solid, pour order 108): 57.506,61.221 60.249,61.221 60.503,60.967 60.503,59.519 60.35,59.366 57.531,59.366 57.404,59.493 57.404,61.119
NetR6_2 on Bottom Layer "Bottom Layer-No Net 24" (solid, pour order 106): 52.883,58.935 52.756,58.808 52.756,57.03 52.502,56.776 52.502,56.242 52.603,56.141 53.873,56.141 53.975,56.242 53.975,58.808 53.848,58.935
HS on Bottom Layer "Bottom Layer-No Net 23" (solid, pour order 104): 90.88,96.368 93.396,96.368 93.98,95.783 93.98,90.964 93.523,90.507 92.456,90.507 91.999,90.964 91.999,93.555 91.669,93.885 90.703,93.885 90.551,94.037 90.551,96.039
VBUS on Bottom Layer "Bottom Layer-No Net 18" (solid, pour order 96): 90.964,90.17 89.992,90.17 89.383,89.56 89.383,86.443 92.939,82.887 92.939,73.133 93.421,72.651 95.936,72.651 97.307,74.022 97.307,79.077 98.704,80.474 101.651,80.474 102.591,81.414 102.591,83.039 102.108,83.522 97.612,83.522
NetC11_1 on Bottom Layer "Bottom Layer-No Net 16" (solid, pour order 92): 84.582,69.704 84.582,68.485 84.836,68.231 91.313,68.231 92.177,69.095 92.177,74.784 91.364,75.597 85.446,75.597 76.937,84.106 73.381,84.106 73.33,84.157 71.78,85.706 71.78,92.539 71.196,93.123 67.92,93.123 67.259,92.463 67.259,81.033 69.291,79.001 75.286,79.001
NetC5_2 on Bottom Layer "Bottom Layer-No Net 14" (solid, remove dead copper, pour order 86): 44.704,88.78 43.028,88.78 41.656,87.408 41.656,85.732 38.176,82.252 34.315,82.252 33.503,83.065 33.503,84.335 36.271,87.103 36.271,92.666 37.211,93.606 44.145,93.606 45.11,92.64 45.11,89.186
NetD1_2 on Bottom Layer "Bottom Layer-No Net 13" (solid, pour order 84): 8.255,83.801 11.811,87.357 14.808,87.357 17.78,90.329 17.78,92.513 18.898,93.631 23.952,93.631 25.07,92.513 25.07,90.075 22.149,87.154 19.075,87.154 11.303,79.382 9.068,79.382 9.042,79.356 8.204,79.356 6.883,80.677 6.883,82.531 8.179,83.827
NetD1_3 on Bottom Layer "Bottom Layer-No Net 12" (solid, remove dead copper, pour order 82): 23.368,84.512 28.219,89.364 28.219,92.513 29.362,93.656 32.512,93.656 33.426,92.742 33.426,87.814 24.994,79.382 19.406,79.382 18.491,80.296 18.491,81.16 18.491,82.785 20.218,84.512
NetC11_2 on Bottom Layer "Bottom Layer-No Net 11" (solid, remove dead copper, pour order 78): 89.383,62.11 85.014,57.741 85.014,44.812 85.75,44.076 91.592,44.076 94.691,47.174 94.691,60.281 92.862,62.11
NetD11_1 on Bottom Layer "Bottom Layer-No Net 8" (solid, remove dead copper, pour order 76): 173.99,89.592 173.736,89.846 173.736,89.948 173.736,93.225 173.533,93.428 169.189,93.428 168.961,93.199 168.961,91.853 171.653,89.161 171.653,86.671 172.06,86.265 173.66,86.265 173.99,86.595
NetC37_2 on Bottom Layer "Bottom Layer-No Net 9" (solid, remove dead copper, pour order 74): 169.062,96.12 169.266,96.323 176.301,96.323 176.505,96.12 176.505,94.825 176.352,94.672 169.215,94.672 169.062,94.825
VOUT on Bottom Layer "Bottom Layer-No Net 10" (solid, remove dead copper, pour order 64): 174.574,94.101 176.403,94.101 176.53,93.974 176.53,89.122 174.447,89.122 174.447,93.974
VOUT on Bottom Layer "Bottom Layer-No Net 10" (solid, remove dead copper, pour order 62): 158.471,94.114 160.299,94.114 160.426,93.987 160.426,89.135 158.344,89.135 158.344,93.987
NetC38_2 on Bottom Layer "Bottom Layer-No Net 9" (solid, remove dead copper, pour order 60): 152.857,96.146 153.06,96.349 160.096,96.349 160.299,96.146 160.299,94.85 160.147,94.698 153.01,94.698 152.857,94.85
NetD12_1 on Bottom Layer "Bottom Layer-No Net 8" (solid, remove dead copper, pour order 58): 157.886,89.567 157.632,89.821 157.632,89.923 157.632,93.199 157.429,93.402 153.086,93.402 152.857,93.174 152.857,91.828 155.55,89.135 155.55,86.646 155.956,86.24 157.556,86.24 157.886,86.57
NetC46_2 on Bottom Layer "Bottom Layer-No Net 6" (solid, pour order 54): 186.709,28.734 182.55,28.734 178.283,33.001 178.283,39.3 178.105,39.478 173.584,39.478 173.482,39.377 173.482,27.261 176.613,24.13 186.487,24.13 187.325,24.968 187.325,28.118
VOUT on Bottom Layer "Bottom Layer-No Net 5" (solid, remove dead copper, pour order 52): 158.623,89.669 160.096,89.669 160.426,89.338 160.426,85.986 160.858,85.554 173.812,85.554 174.447,86.189 174.447,89.313 174.803,89.669 176.124,89.669 176.53,89.262 176.53,86.316 177.292,85.554 185.471,85.554 188.976,82.049 188.976,32.163 187.223,30.41 183.21,30.41 179.781,33.839 179.781,45.676 179.781,72.346 174.65,77.477 159.766,77.477 158.344,78.899 158.344,89.389
NetC2_1 on Bottom Layer "Bottom Layer-No Net 3" (solid, pour order 50): 11.862,71.965 12.268,71.558 12.268,69.831 11.76,69.323 10.947,69.323 9.855,68.231 9.855,64.294 12.471,61.678 12.471,54.083 11.43,53.042 8.255,53.042 7.188,54.109 7.188,71.381 7.772,71.965
NetC2_2 on Bottom Layer "Bottom Layer-No Net 2" (solid, pour order 48): 22.352,71.939 25.425,68.866 25.425,54.49 23.978,53.042 20.777,53.042 19.812,54.007 19.812,60.916 21.615,62.719 21.615,68.282 20.549,69.349 18.593,69.349 18.034,69.907 18.034,71.457 18.517,71.939
NetR2_1 on Bottom Layer "Bottom Layer-No Net 1" (solid, pour order 46): 11.455,67.24 14.834,67.24 14.91,67.164 14.91,65.335 14.783,65.208 11.43,65.208 11.379,65.259 11.379,67.164
NetR1_1 on Bottom Layer "Bottom Layer-No Net 1" (solid, pour order 44): 16.561,67.24 19.939,67.24 20.015,67.164 20.015,65.335 19.888,65.208 16.535,65.208 16.485,65.259 16.485,67.164
NetC1_1 on Bottom Layer "Bottom Layer-No Net" (solid, pour order 42): 24.054,48.089 20.549,48.089 19.812,47.352 19.812,37.776 18.212,36.176 11.735,36.176 8.28,32.722 8.28,31.325 9.017,30.588 10.414,30.588 13.538,33.712 20.015,33.712 21.285,32.442 21.285,30.074 22.53,28.829 25.222,28.829 26.518,30.124 26.518,41.409 24.74,43.187 24.74,47.403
